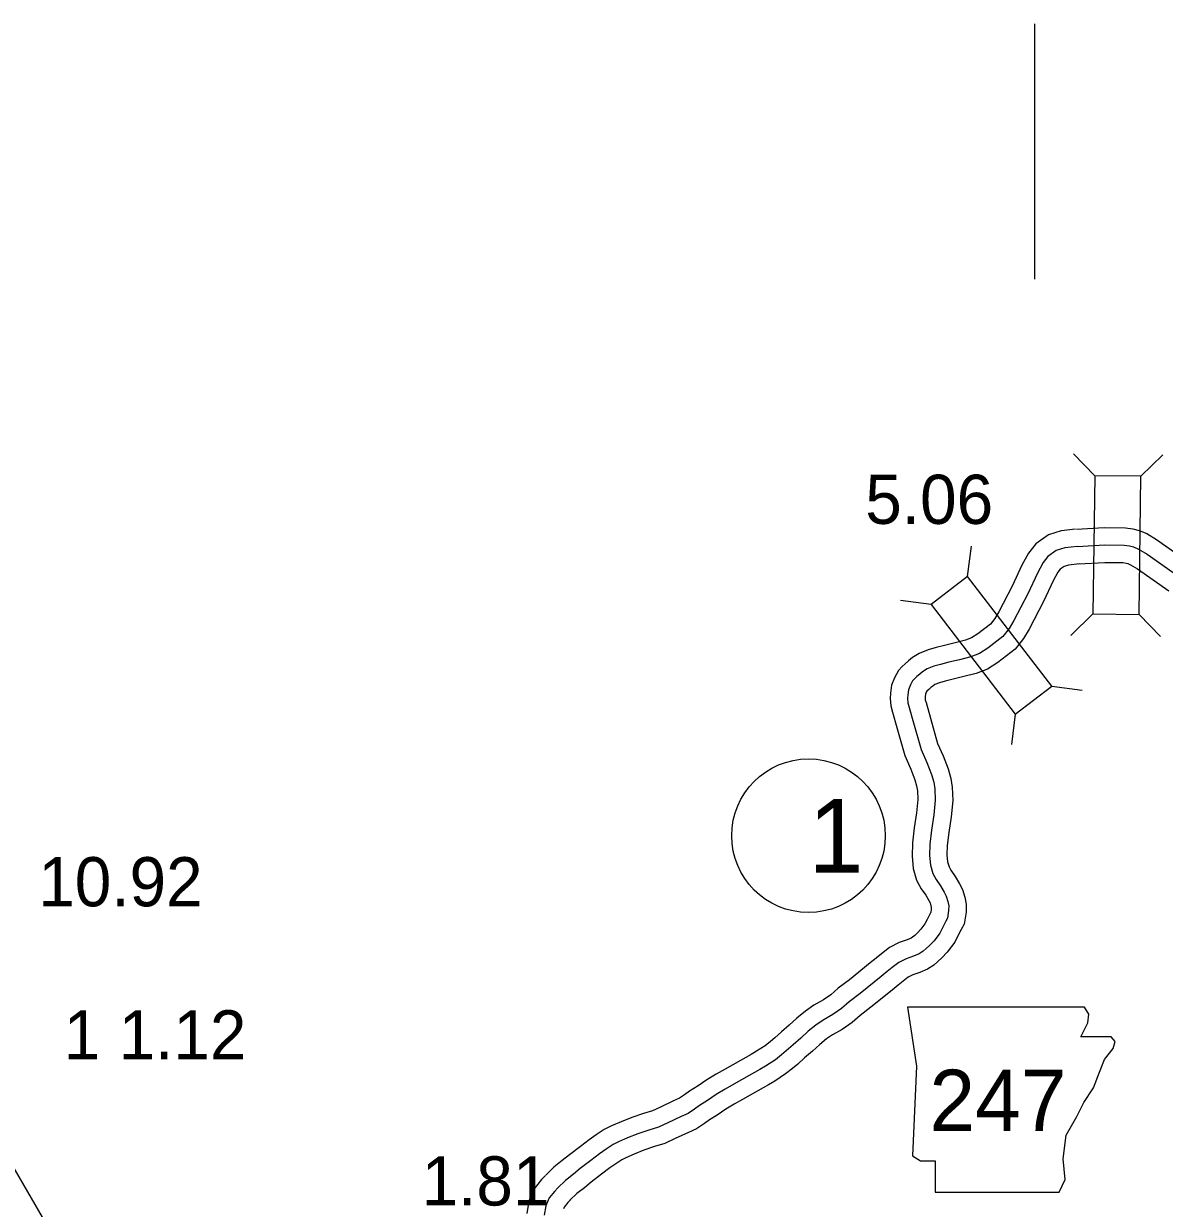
# Model space of a CAD drawing. Extents: x 31699 to 244310, y -8841 to 11474.
# Drawn here: x 98557 to 99211, y 4320 to 4999 of the extents above; entities that cross this region are included whole.
import ezdxf

# ---------------------------------------------------------------- set-up
doc = ezdxf.new("R2010")
doc.units = 0
for name, color, linetype in [('B_Logo', 7, 'Continuous'), ('Default', 7, 'Continuous'), ('G-ANNO-TEXT', 7, 'Continuous'), ('R_Border Notes', 7, 'Continuous'), ('R_XS_EARTHWORK_STAGE1', 7, 'Continuous'), ('R_XS_EARTHWORK_STAGE2', 7, 'Continuous'), ('S_WALL', 7, 'Continuous')]:
    doc.layers.add(name, color=color, linetype=linetype)

msp = doc.modelspace()

# ---------------------------------------------------------------- linework, layer by layer
at = {"layer": 'B_Logo'}
for points in [[(99160.86, 4699.6), (99153.62, 4698.74), (99148.72, 4697.26), (99143.92, 4693.84), (99141.19, 4690.32), (99137.96, 4684.33), (99132.44, 4672.43), (99124.45, 4657.14), (99121.67, 4652.56), (99118.02, 4647.96), (99109.42, 4641.34), (99104.68, 4638.33), (99099.66, 4636.37), (99093.23, 4634.73), (99087.14, 4633.22), (99082.43, 4632.01), (99078.53, 4630.94), (99074.69, 4629.41), (99072.13, 4627.83), (99070.42, 4626.46), (99068.85, 4625.04), (99067.41, 4623.68), (99066.36, 4622.59), (99065.07, 4620.24), (99064.05, 4617.55), (99063.63, 4614.67), (99063.54, 4612.6), (99063.71, 4610), (99064.49, 4607.35), (99066.97, 4598.58), (99071.29, 4583.31), (99074.61, 4575.76), (99077.19, 4569), (99078.46, 4564.55), (99079.06, 4560.69), (99079.37, 4554.29), (99078.51, 4545.87), (99077.27, 4537.05), (99076.2, 4529.09), (99076.05, 4522.55), (99076.54, 4517.02), (99077.95, 4512.24), (99079.81, 4508.8), (99082.4, 4505.18), (99084.46, 4501.54), (99085.69, 4499.23), (99086.61, 4496.17), (99087.12, 4493.71), (99087.03, 4490.98), (99086.38, 4486.56), (99085.47, 4484.95), (99083.6, 4481.44), (99082.06, 4478.08), (99078.68, 4473.75), (99076.13, 4471.04), (99074.23, 4469.34), (99072.46, 4467.78), (99070.15, 4466.27), (99066.92, 4464.95), (99062.62, 4463.4), (99058.53, 4461.33), (99054.72, 4458.4), (99051.83, 4456.02), (99048.35, 4453.29), (99036.35, 4443.47), (99030.04, 4438.7), (99025.58, 4434.88), (99020.58, 4431.4), (99015.18, 4428.3), (99010.97, 4425.43), (99006.58, 4421.82), (99002.32, 4417.94), (98997.86, 4414.06), (98993.99, 4410.59), (98991.24, 4408.28), (98987.76, 4405.48), (98982.17, 4401.85), (98978.8, 4399.93), (98972.68, 4396.42), (98963.91, 4391.46), (98958.97, 4388.71), (98953.9, 4385.56), (98948.9, 4382.27), (98944.23, 4379.32), (98941.34, 4377.13), (98937.72, 4374.8), (98933.69, 4372.93), (98926.17, 4369.4), (98920.82, 4366.91), (98915.32, 4365.28), (98908.98, 4363.04), (98903.09, 4360.74), (98897.94, 4358.51), (98894.71, 4356.92), (98890.7, 4354.25), (98886.88, 4351.59), (98882.09, 4347.9), (98875.91, 4343.26), (98871.98, 4339.99), (98867.45, 4336.38), (98863.13, 4332.23)], [(99160.86, 4699.6), (99176.37, 4700.47), (99187.63, 4700.31), (99190.64, 4699.93), (99192.99, 4699.33), (99195.89, 4698.07), (99200.7, 4695.14), (99218.99, 4682.36)], [(98863.13, 4332.23), (98861.3, 4330.33), (98858.1, 4326.34), (98857.08, 4324.06), (98856.19, 4321.77), (98855.28, 4316.55)]]:
    msp.add_lwpolyline(points, dxfattribs=at)
at = {"layer": 'Default'}
msp.add_line((99136.23, 4999.1), (99136.23, 4852.8), dxfattribs=at)
at = {"layer": 'G-ANNO-TEXT'}
msp.add_lwpolyline([(99063.5, 4435.65), (99068.58, 4401.81), (99066.32, 4350.5), (99070.83, 4347.68), (99079.29, 4347.68), (99079.29, 4329.63), (99150.35, 4329.63), (99153.73, 4336.96), (99152.6, 4348.8), (99154.29, 4362.34), (99160.5, 4373.05), (99164.44, 4380.95), (99170.08, 4389.41), (99173.47, 4398.43), (99176.29, 4405.76), (99181.36, 4411.96), (99182.49, 4415.91), (99180.23, 4418.73), (99162.75, 4418.73), (99166.7, 4426.63), (99167.26, 4431.7), (99164.92, 4435.6)], close=True, dxfattribs=at)
at = {"layer": 'R_Border Notes'}
msp.add_circle((99006.72, 4533.89), 44, dxfattribs=at)
at = {"layer": 'R_XS_EARTHWORK_STAGE1'}
for p, q in [((99170.8, 4740.15), (99158.53, 4752.76)), ((99197.2, 4739.79), (99209.81, 4752.06)), ((99097.86, 4682.41), (99100.13, 4699.86)), ((99076.93, 4666.31), (99059.48, 4668.59)), ((99169.72, 4660.96), (99157.1, 4648.68)), ((99196.11, 4660.6), (99208.39, 4647.98)), ((99146.15, 4619.64), (99163.6, 4617.36)), ((99125.23, 4603.54), (99122.95, 4586.09))]:
    msp.add_line(p, q, dxfattribs=at)
for points in [[(99170.8, 4740.15), (99169.72, 4660.96), (99196.11, 4660.6), (99197.2, 4739.79)], [(99146.15, 4619.64), (99097.86, 4682.41), (99076.93, 4666.31), (99125.23, 4603.54)]]:
    msp.add_lwpolyline(points, close=True, dxfattribs=at)
at = {"layer": 'R_XS_EARTHWORK_STAGE2'}
for points in [[(99160.3, 4709.58), (99176.15, 4710.47), (99188.33, 4710.31), (99192.52, 4709.77), (99196.23, 4708.82), (99200.5, 4706.97), (99206.18, 4703.51), (99224.83, 4690.47)], [(99159.68, 4709.53), (99151.56, 4708.57), (99144.25, 4706.35), (99136.93, 4701.13), (99132.78, 4695.8), (99129.02, 4688.81), (99123.47, 4676.85), (99115.74, 4662.06), (99113.45, 4658.28), (99110.95, 4655.14), (99103.68, 4649.54), (99100.14, 4647.29), (99096.6, 4645.91), (99090.79, 4644.43), (99084.69, 4642.92), (99079.87, 4641.67), (99075.34, 4640.44), (99070.19, 4638.37), (99066.37, 4636.03), (99063.93, 4634.08), (99062.05, 4632.38), (99060.37, 4630.79), (99058.23, 4628.57), (99055.97, 4624.43), (99054.31, 4620.07), (99053.67, 4615.63), (99053.52, 4612.5), (99053.81, 4608.24), (99054.88, 4604.58), (99057.35, 4595.86), (99061.85, 4579.92), (99065.36, 4571.97), (99067.69, 4565.84), (99068.67, 4562.4), (99069.1, 4559.69), (99069.34, 4554.56), (99068.58, 4547.08), (99067.36, 4538.41), (99066.22, 4529.87), (99066.04, 4522.22), (99066.67, 4515.14), (99068.66, 4508.41), (99071.31, 4503.5), (99073.96, 4499.79), (99075.7, 4496.72), (99076.4, 4495.39), (99076.91, 4493.72), (99077.09, 4492.85), (99077.06, 4491.87), (99076.75, 4489.84), (99076.7, 4489.74), (99074.64, 4485.88), (99073.46, 4483.32), (99071.08, 4480.27), (99069.14, 4478.2), (99067.58, 4476.81), (99066.38, 4475.75), (99065.48, 4475.16), (99063.34, 4474.29), (99058.66, 4472.61), (99053.17, 4469.83), (99048.48, 4466.22), (99045.56, 4463.81), (99042.1, 4461.09), (99030.16, 4451.33), (99023.77, 4446.49), (99019.45, 4442.8), (99015.23, 4439.85), (99009.87, 4436.78), (99004.97, 4433.44), (99000.03, 4429.38), (98995.67, 4425.41), (98991.24, 4421.56), (98987.43, 4418.14), (98984.89, 4416), (98981.89, 4413.59), (98976.95, 4410.39), (98973.84, 4408.6), (98967.73, 4405.11), (98959.02, 4400.19), (98953.89, 4397.33), (98948.51, 4393.98), (98943.48, 4390.68), (98938.53, 4387.55), (98935.61, 4385.34), (98932.88, 4383.58), (98929.46, 4382), (98921.93, 4378.46), (98917.27, 4376.29), (98912.24, 4374.8), (98905.49, 4372.41), (98899.29, 4369.99), (98893.75, 4367.6), (98889.71, 4365.61), (98885.06, 4362.51), (98880.97, 4359.65), (98876.04, 4355.86), (98869.71, 4351.11), (98865.66, 4347.74), (98860.85, 4343.91), (98856.21, 4339.45)], [(99161.42, 4689.61), (99176.58, 4690.46), (99186.93, 4690.32), (99188.76, 4690.09), (99189.74, 4689.84), (99191.28, 4689.17), (99195.23, 4686.76), (99213.14, 4674.24)], [(99162.03, 4689.67), (99155.67, 4688.91), (99153.19, 4688.16), (99150.92, 4686.54), (99149.6, 4684.85), (99146.91, 4679.85), (99141.42, 4668), (99133.17, 4652.23), (99129.89, 4646.84), (99125.09, 4640.78), (99115.17, 4633.14), (99109.22, 4629.36), (99102.72, 4626.83), (99095.67, 4625.03), (99089.59, 4623.53), (99085, 4622.34), (99081.71, 4621.44), (99079.2, 4620.44), (99077.89, 4619.63), (99076.91, 4618.85), (99075.64, 4617.7), (99074.48, 4616.61), (99074.17, 4616.04), (99073.79, 4615.03), (99073.6, 4613.72), (99073.55, 4612.71), (99073.62, 4611.77), (99074.1, 4610.11), (99076.59, 4601.31), (99080.72, 4586.7), (99083.86, 4579.56), (99086.68, 4572.16), (99088.25, 4566.7), (99089.02, 4561.7), (99089.39, 4554.03), (99088.44, 4544.67), (99087.17, 4535.68), (99086.19, 4528.31), (99086.06, 4522.87), (99086.41, 4518.9), (99087.25, 4516.07), (99088.31, 4514.1), (99090.84, 4510.56), (99093.22, 4506.36), (99094.98, 4503.06), (99096.32, 4498.63), (99097.15, 4494.58), (99097.01, 4490.08), (99096, 4483.28), (99094.25, 4480.15), (99092.57, 4477), (99090.66, 4472.85), (99086.27, 4467.24), (99083.12, 4463.88), (99080.87, 4461.87), (99078.54, 4459.81), (99074.83, 4457.38), (99070.5, 4455.61), (99066.58, 4454.2), (99063.89, 4452.84), (99060.96, 4450.58), (99058.1, 4448.22), (99054.6, 4445.48), (99042.53, 4435.61), (99036.31, 4430.9), (99031.71, 4426.96), (99025.94, 4422.94), (99020.49, 4419.82), (99016.98, 4417.42), (99013.12, 4414.25), (99008.96, 4410.47), (99004.48, 4406.57), (99000.55, 4403.04), (98997.59, 4400.55), (98993.63, 4397.37), (98987.38, 4393.31), (98983.77, 4391.25), (98977.62, 4387.73), (98968.81, 4382.74), (98964.05, 4380.09), (98959.29, 4377.13), (98954.32, 4373.86), (98949.92, 4371.09), (98947.07, 4368.93), (98942.55, 4366.02), (98937.92, 4363.87), (98930.4, 4360.35), (98924.37, 4357.53), (98918.41, 4355.77), (98912.46, 4353.67), (98906.9, 4351.49), (98902.13, 4349.43), (98899.71, 4348.24), (98896.33, 4345.99), (98892.8, 4343.52), (98888.14, 4339.94), (98882.12, 4335.41), (98878.29, 4332.23), (98874.04, 4328.84), (98870.05, 4325.01)], [(98567.84, 4315.43), (98543.87, 4356.58)], [(98855.93, 4339.17), (98853.78, 4336.94), (98849.5, 4331.59), (98847.85, 4327.92), (98846.51, 4324.48), (98845.29, 4317.51)], [(98870.33, 4325.29), (98868.82, 4323.73), (98866.71, 4321.09), (98866.3, 4320.19)]]:
    msp.add_lwpolyline(points, dxfattribs=at)

# ---------------------------------------------------------------- texts
at = {"layer": 'G-ANNO-TEXT'}
msp.add_text('247', height=35.2, dxfattribs=at).set_placement((99076.02, 4364.62))
at = {"layer": 'R_Border Notes'}
msp.add_text('1', height=42.24, dxfattribs=at).set_placement((99006.72, 4512.77))
at = {"layer": 'S_WALL'}
for s, p in [('5.06', (99039.24, 4712.53)), ('10.92', (98565.34, 4493.44)), ('1 1.12', (98579.97, 4405.7)), ('1.81', (98784.98, 4322.03))]:
    msp.add_text(s, height=28.16, dxfattribs=at).set_placement(p)

doc.saveas('drawing.dxf')
